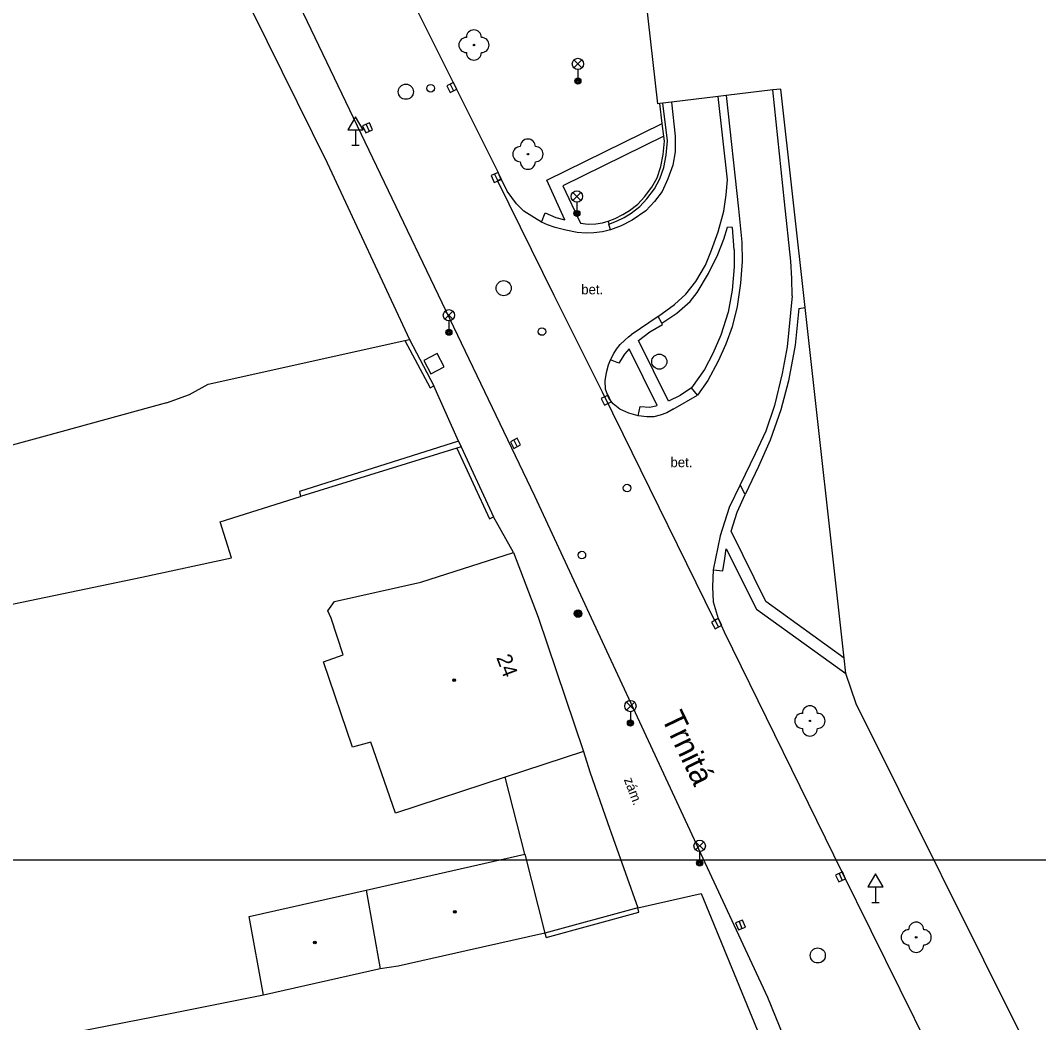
# Model space of a CAD drawing. Extents: x -598341 to -594502, y -1162301 to -1161406.
# Drawn here: x -597845.9 to -597778.6, y -1161741.3 to -1161675 of the extents above; entities that cross this region are included whole.
import ezdxf

# ---------------------------------------------------------------- set-up
doc = ezdxf.new("R2010")
doc.units = 0
for name, color, linetype in [('OKRAJ', 7, 'Continuous'), ('Vrstva 10', 7, 'Continuous'), ('Vrstva 11', 7, 'Continuous'), ('Vrstva 22', 7, 'Continuous'), ('Vrstva 25', 7, 'Continuous'), ('Vrstva 26', 7, 'Continuous'), ('Vrstva 27', 7, 'Continuous'), ('Vrstva 28', 7, 'Continuous'), ('Vrstva 31', 7, 'Continuous'), ('Vrstva 33', 7, 'Continuous'), ('Vrstva 34', 7, 'Continuous'), ('Vrstva 39', 7, 'Continuous'), ('Vrstva 40', 7, 'Continuous'), ('Vrstva 46', 7, 'Continuous'), ('Vrstva 49', 7, 'Continuous'), ('Vrstva 5', 7, 'Continuous'), ('Vrstva 7', 7, 'Continuous'), ('Vrstva 8', 7, 'Continuous')]:
    doc.layers.add(name, color=color, linetype=linetype)

msp = doc.modelspace()

# ---------------------------------------------------------------- linework, layer by layer
at = {"layer": 'OKRAJ'}
msp.add_line((-598126.97, -1161730.491), (-597723.77, -1161730.491), dxfattribs=at)
at = {"layer": 'Vrstva 10'}
for p, q in [((-597811.93, -1161706.44), (-597830.41, -1161667.86)), ((-597800.5, -1161731.02), (-597811.93, -1161706.44)), ((-597796.51, -1161739.61), (-597800.5, -1161731.02)), ((-597784.98, -1161767.75), (-597796.51, -1161739.61))]:
    msp.add_line(p, q, dxfattribs=at)
for points in [[(-597830.5, -1161652.45), (-597830.04, -1161653.37), (-597820.72, -1161672.28), (-597814.35, -1161685.04)], [(-597794.91, -1161693.2), (-597794.93, -1161692.06), (-597794.99, -1161690.9), (-597795.4, -1161686.98), (-597796.19, -1161679.58)], [(-597799.19, -1161685.52), (-597799.8, -1161680.01)], [(-597799.27, -1161679.95), (-597798.46, -1161687.44), (-597798.24, -1161689.64)], [(-597802.89, -1161680.38), (-597802.64, -1161682.63)], [(-597802.64, -1161682.63), (-597802.64, -1161683.68), (-597802.8, -1161684.55), (-597803.13, -1161685.47), (-597803.51, -1161686.29), (-597804, -1161686.95), (-597804.59, -1161687.58), (-597805.48, -1161688.19), (-597806.21, -1161688.57), (-597806.91, -1161688.83)], [(-597814.14, -1161685.47), (-597814.35, -1161685.04)], [(-597811.47, -1161688.32), (-597811.95, -1161688.05), (-597812.65, -1161687.59), (-597813.14, -1161687.11), (-597813.75, -1161686.28), (-597814.14, -1161685.47)], [(-597803.75, -1161694.55), (-597802.69, -1161693.77), (-597801.93, -1161693.09), (-597801.28, -1161692.25), (-597800.64, -1161691.17), (-597800.24, -1161690.18), (-597799.8, -1161688.96), (-597799.42, -1161687.59), (-597799.26, -1161686.51), (-597799.19, -1161685.52)], [(-597806.91, -1161688.83), (-597807.45, -1161688.97), (-597808.01, -1161689.04), (-597808.53, -1161689.06), (-597809.12, -1161689.02), (-597809.86, -1161688.86), (-597810.57, -1161688.68), (-597811.08, -1161688.5), (-597811.47, -1161688.32)], [(-597798.24, -1161689.64), (-597798.22, -1161690.93), (-597798.31, -1161692.36), (-597798.55, -1161693.91), (-597798.86, -1161695.25), (-597799.28, -1161696.4), (-597799.8, -1161697.51), (-597800.48, -1161698.8), (-597801.16, -1161699.77)], [(-597794.91, -1161693.2), (-597795.24, -1161696.57), (-597795.57, -1161698.34), (-597796.06, -1161700.45), (-597796.65, -1161702.14), (-597797.35, -1161703.65), (-597798.35, -1161705.7)], [(-597803.77, -1161694.56), (-597805.54, -1161695.77)], [(-597803.75, -1161694.55), (-597803.77, -1161694.56)], [(-597806.92, -1161697.42), (-597806.7, -1161697.02), (-597806.52, -1161696.73), (-597806.27, -1161696.42), (-597805.97, -1161696.12), (-597805.72, -1161695.91), (-597805.54, -1161695.77)], [(-597805.09, -1161701.14), (-597805.7, -1161700.96), (-597806.31, -1161700.69), (-597806.75, -1161700.34), (-597807.03, -1161699.96), (-597807.24, -1161699.37), (-597807.27, -1161698.83), (-597807.18, -1161698.26), (-597807.05, -1161697.76), (-597806.92, -1161697.42)], [(-597802.77, -1161700.7), (-597801.16, -1161699.77)], [(-597802.77, -1161700.7), (-597803.19, -1161700.93), (-597803.64, -1161701.1), (-597804.06, -1161701.19), (-597804.52, -1161701.21), (-597805.09, -1161701.14)], [(-597798.35, -1161705.7), (-597799.06, -1161707.2), (-597799.67, -1161709.06), (-597800.12, -1161711.31)], [(-597800.12, -1161711.31), (-597800.17, -1161712.44), (-597800.12, -1161713.43), (-597799.8, -1161714.53)], [(-597799.8, -1161714.53), (-597799.4, -1161715.41)], [(-597799.4, -1161715.41), (-597791.61, -1161731.3), (-597783.95, -1161746.81), (-597776.03, -1161762.85), (-597771.77, -1161771.52), (-597769.76, -1161775.59), (-597768.73, -1161777.72)]]:
    msp.add_lwpolyline(points, dxfattribs=at)
at = {"layer": 'Vrstva 11'}
for p, q in [((-597814.14, -1161685.47), (-597814.38, -1161685.59)), ((-597829.87, -1161739.44), (-597836.15, -1161740.7)), ((-597836.15, -1161740.7), (-597845.05, -1161742.44))]:
    msp.add_line(p, q, dxfattribs=at)
for points in [[(-597811.47, -1161688.32), (-597811.23, -1161687.7), (-597810.53, -1161688.01), (-597809.93, -1161688.18), (-597811.13, -1161685.55), (-597803.5, -1161681.79)], [(-597803.39, -1161682.64), (-597810.07, -1161685.93), (-597808.9, -1161688.4)], [(-597814.38, -1161685.59), (-597810.67, -1161693.15), (-597807.47, -1161699.55)], [(-597808.9, -1161688.4), (-597808.39, -1161688.45), (-597807.89, -1161688.43), (-597807.45, -1161688.38), (-597807.08, -1161688.27)], [(-597806.91, -1161688.83), (-597807.02, -1161688.46)], [(-597803.52, -1161695.01), (-597802.52, -1161694.34), (-597801.65, -1161693.57), (-597801.18, -1161692.98), (-597800.43, -1161691.73), (-597799.82, -1161690.47), (-597799.42, -1161689.46), (-597799.19, -1161688.66)], [(-597798.73, -1161690.15), (-597798.84, -1161688.68), (-597799.19, -1161688.66)], [(-597798.73, -1161690.15), (-597798.74, -1161691.29), (-597798.86, -1161692.82), (-597799.14, -1161694.27), (-597799.61, -1161695.8), (-597800.15, -1161697.02), (-597800.69, -1161698.08), (-597801.55, -1161699.29)], [(-597794.47, -1161694.04), (-597794.7, -1161696.46), (-597795.14, -1161698.81), (-597795.66, -1161700.73), (-597796.36, -1161702.75), (-597797.14, -1161704.49), (-597798.02, -1161706.33)], [(-597794.47, -1161694.04), (-597794.05, -1161693.97)], [(-597801.55, -1161699.29), (-597802.31, -1161699.79), (-597803.09, -1161700.16), (-597805.06, -1161696.15), (-597804.31, -1161695.58), (-597803.47, -1161695.1), (-597803.52, -1161695.01)], [(-597803.52, -1161695.01), (-597803.77, -1161694.56)], [(-597805.09, -1161701.14), (-597804.96, -1161700.52), (-597804.31, -1161700.56), (-597803.84, -1161700.46), (-597805.69, -1161696.7), (-597806, -1161697.06), (-597806.36, -1161697.65), (-597806.92, -1161697.42)], [(-597807.47, -1161699.55), (-597806.11, -1161702.33), (-597804.33, -1161705.91), (-597800.05, -1161714.62), (-597799.8, -1161714.53)], [(-597801.16, -1161699.77), (-597801.55, -1161699.29)], [(-597798.02, -1161706.33), (-597798.35, -1161705.7)], [(-597791.46, -1161717.16), (-597796.64, -1161713.41), (-597798.94, -1161708.76), (-597798.54, -1161707.5), (-597798.02, -1161706.33)], [(-597800.12, -1161711.31), (-597799.48, -1161711.38), (-597799.35, -1161710.56), (-597799.26, -1161709.93), (-597797.26, -1161713.92), (-597791.35, -1161718.18)], [(-597808.71, -1161723.34), (-597808.28, -1161724.67), (-597807.11, -1161728.04), (-597806.75, -1161729.08), (-597805.12, -1161733.68)]]:
    msp.add_lwpolyline(points, dxfattribs=at)
at = {"layer": 'Vrstva 22'}
for centre in [(-597815.95, -1161676.61), (-597812.38, -1161683.83), (-597793.73, -1161721.31), (-597786.7, -1161735.62)]:
    msp.add_circle(centre, 0.05, dxfattribs=at)
for centre, start, end in [((-597815.95, -1161676.11), 0, 180), ((-597816.45, -1161676.61), 90, 270), ((-597815.45, -1161676.61), 270, 90), ((-597815.95, -1161677.11), 180, 0), ((-597812.38, -1161683.33), 0, 180), ((-597812.88, -1161683.83), 90, 270), ((-597811.88, -1161683.83), 270, 90), ((-597812.38, -1161684.33), 180, 0), ((-597793.73, -1161720.81), 0, 180), ((-597794.23, -1161721.31), 90, 270), ((-597793.23, -1161721.31), 270, 90), ((-597793.73, -1161721.81), 180, 0), ((-597786.7, -1161735.12), 0, 180), ((-597787.2, -1161735.62), 90, 270), ((-597786.2, -1161735.62), 270, 90), ((-597786.7, -1161736.12), 180, 0)]:
    msp.add_arc(centre, 0.5, start, end, dxfattribs=at)
at = {"layer": 'Vrstva 25'}
for radius in [0.25, 0.2, 0.15, 0.1, 0.05]:
    msp.add_circle((-597809.06, -1161714.21), radius, dxfattribs=at)
at = {"layer": 'Vrstva 26'}
msp.add_lwpolyline([(-597819.265, -1161697.481), (-597818.799, -1161698.365), (-597817.915, -1161697.899), (-597818.381, -1161697.015)], close=True, dxfattribs=at)
at = {"layer": 'Vrstva 27'}
for p, q in [((-597817.521, -1161679.196), (-597817.299, -1161679.644)), ((-597823.082, -1161681.862), (-597822.878, -1161682.318)), ((-597814.582, -1161685.142), (-597814.378, -1161685.598)), ((-597807.308, -1161699.874), (-597807.092, -1161700.326)), ((-597813.318, -1161702.739), (-597813.082, -1161703.181)), ((-597800.006, -1161714.658), (-597799.774, -1161715.102)), ((-597791.803, -1161731.402), (-597791.597, -1161731.858)), ((-597798.415, -1161734.579), (-597798.225, -1161735.041))]:
    msp.add_line(p, q, dxfattribs=at)
for points in [[(-597817.745, -1161679.307), (-597817.523, -1161679.755), (-597817.075, -1161679.533), (-597817.297, -1161679.085)], [(-597823.31, -1161681.965), (-597823.106, -1161682.421), (-597822.65, -1161682.216), (-597822.854, -1161681.76)], [(-597814.81, -1161685.245), (-597814.606, -1161685.701), (-597814.15, -1161685.496), (-597814.354, -1161685.04)], [(-597807.533, -1161699.982), (-597807.318, -1161700.433), (-597806.867, -1161700.218), (-597807.082, -1161699.767)], [(-597813.538, -1161702.857), (-597813.303, -1161703.298), (-597812.862, -1161703.063), (-597813.097, -1161702.622)], [(-597800.227, -1161714.774), (-597799.996, -1161715.217), (-597799.553, -1161714.986), (-597799.784, -1161714.543)], [(-597792.031, -1161731.506), (-597791.824, -1161731.961), (-597791.369, -1161731.754), (-597791.576, -1161731.299)], [(-597798.646, -1161734.674), (-597798.456, -1161735.136), (-597797.994, -1161734.946), (-597798.184, -1161734.484)]]:
    msp.add_lwpolyline(points, close=True, dxfattribs=at)
for centre in [(-597820.45, -1161679.7), (-597813.98, -1161692.69), (-597803.69, -1161697.55), (-597793.21, -1161736.82)]:
    msp.add_circle(centre, 0.5, dxfattribs=at)
at = {"layer": 'Vrstva 28'}
for centre in [(-597818.81, -1161679.47), (-597811.45, -1161695.56), (-597805.82, -1161705.91)]:
    msp.add_circle(centre, 0.25, dxfattribs=at)
at = {"layer": 'Vrstva 31'}
msp.add_circle((-597808.81, -1161710.34), 0.25, dxfattribs=at)
at = {"layer": 'Vrstva 33'}
for p, q in [((-597809.335, -1161678.13), (-597808.805, -1161677.6)), ((-597809.335, -1161677.6), (-597808.805, -1161678.13)), ((-597809.07, -1161678.24), (-597809.07, -1161678.99)), ((-597809.405, -1161686.89), (-597808.875, -1161686.36)), ((-597809.405, -1161686.36), (-597808.875, -1161686.89)), ((-597809.14, -1161687), (-597809.14, -1161687.75)), ((-597817.865, -1161694.75), (-597817.335, -1161694.22)), ((-597817.865, -1161694.22), (-597817.335, -1161694.75)), ((-597817.6, -1161694.86), (-597817.6, -1161695.61)), ((-597805.865, -1161720.59), (-597805.335, -1161720.06)), ((-597805.865, -1161720.06), (-597805.335, -1161720.59)), ((-597805.6, -1161720.7), (-597805.6, -1161721.45)), ((-597801.285, -1161729.84), (-597800.755, -1161729.31)), ((-597801.285, -1161729.31), (-597800.755, -1161729.84)), ((-597801.02, -1161729.95), (-597801.02, -1161730.7))]:
    msp.add_line(p, q, dxfattribs=at)
for centre, radius in [((-597809.07, -1161677.865), 0.375), ((-597809.07, -1161678.99), 0.2), ((-597809.07, -1161678.99), 0.145), ((-597809.07, -1161678.99), 0.0876), ((-597809.14, -1161686.625), 0.375), ((-597809.14, -1161687.75), 0.2), ((-597809.14, -1161687.75), 0.145), ((-597809.14, -1161687.75), 0.0876), ((-597817.6, -1161694.485), 0.375), ((-597817.6, -1161695.61), 0.2), ((-597817.6, -1161695.61), 0.145), ((-597817.6, -1161695.61), 0.0876), ((-597805.6, -1161720.325), 0.375), ((-597805.6, -1161721.45), 0.2), ((-597805.6, -1161721.45), 0.145), ((-597805.6, -1161721.45), 0.0876), ((-597801.02, -1161729.575), 0.375), ((-597801.02, -1161730.7), 0.2), ((-597801.02, -1161730.7), 0.145), ((-597801.02, -1161730.7), 0.0876)]:
    msp.add_circle(centre, radius, dxfattribs=at)
at = {"layer": 'Vrstva 34'}
for p, q in [((-597823.78, -1161682.222), (-597823.78, -1161683.24)), ((-597824.03, -1161683.24), (-597823.53, -1161683.24)), ((-597789.39, -1161732.292), (-597789.39, -1161733.31)), ((-597789.64, -1161733.31), (-597789.14, -1161733.31))]:
    msp.add_line(p, q, dxfattribs=at)
for points in [[(-597824.28, -1161682.222), (-597823.28, -1161682.222), (-597823.78, -1161681.356)], [(-597789.89, -1161732.292), (-597788.89, -1161732.292), (-597789.39, -1161731.426)]]:
    msp.add_lwpolyline(points, close=True, dxfattribs=at)
at = {"layer": 'Vrstva 39'}
for centre, radius in [((-597817.26, -1161718.61), 0.09), ((-597817.26, -1161718.61), 0.0398), ((-597817.22, -1161733.93), 0.09), ((-597817.22, -1161733.93), 0.0398), ((-597826.47, -1161735.97), 0.09), ((-597826.47, -1161735.97), 0.0398)]:
    msp.add_circle(centre, radius, dxfattribs=at)
at = {"layer": 'Vrstva 5'}
for p, q in [((-597803.79, -1161680.49), (-597807.22, -1161650.28)), ((-597796.19, -1161679.58), (-597799.27, -1161679.95)), ((-597795.66, -1161679.52), (-597796.19, -1161679.58)), ((-597794.05, -1161693.97), (-597795.66, -1161679.52)), ((-597799.8, -1161680.01), (-597802.89, -1161680.38)), ((-597799.27, -1161679.95), (-597799.8, -1161680.01)), ((-597803.66, -1161680.48), (-597803.79, -1161680.49)), ((-597803.46, -1161680.45), (-597803.66, -1161680.48)), ((-597802.89, -1161680.38), (-597803.46, -1161680.45)), ((-597791.46, -1161717.16), (-597794.05, -1161693.97)), ((-597819.46, -1161712.13), (-597813.34, -1161710.17)), ((-597813.34, -1161710.17), (-597811.71, -1161714.44)), ((-597825.17, -1161713.42), (-597819.46, -1161712.13)), ((-597825.6, -1161714.04), (-597825.17, -1161713.42)), ((-597825.39, -1161714.51), (-597825.6, -1161714.04)), ((-597824.6, -1161716.94), (-597825.39, -1161714.51)), ((-597811.71, -1161714.44), (-597808.71, -1161723.34)), ((-597825.9, -1161717.4), (-597824.6, -1161716.94)), ((-597791.35, -1161718.18), (-597791.46, -1161717.16)), ((-597823.97, -1161723.04), (-597825.9, -1161717.4)), ((-597790.68, -1161720.18), (-597791.35, -1161718.18)), ((-597767.04, -1161767.55), (-597790.68, -1161720.18)), ((-597822.76, -1161722.71), (-597823.97, -1161723.04)), ((-597821.14, -1161727.42), (-597822.76, -1161722.71)), ((-597808.71, -1161723.34), (-597813.89, -1161725.04)), ((-597813.89, -1161725.04), (-597821.14, -1161727.42)), ((-597823.08, -1161732.5), (-597812.59, -1161730.12)), ((-597812.59, -1161730.12), (-597811.26, -1161735.34)), ((-597830.81, -1161734.25), (-597823.08, -1161732.5)), ((-597823.08, -1161732.5), (-597822.14, -1161737.7)), ((-597829.87, -1161739.44), (-597830.81, -1161734.25)), ((-597811.26, -1161735.34), (-597816.46, -1161736.51)), ((-597816.46, -1161736.51), (-597820.97, -1161737.54)), ((-597820.97, -1161737.54), (-597822.14, -1161737.7)), ((-597822.14, -1161737.7), (-597829.87, -1161739.44))]:
    msp.add_line(p, q, dxfattribs=at)
at = {"layer": 'Vrstva 7'}
for p, q in [((-597833.1, -1161669.29), (-597829.64, -1161676.34)), ((-597829.64, -1161676.34), (-597825.66, -1161684.4)), ((-597825.66, -1161684.4), (-597820.21, -1161696.09)), ((-597807.08, -1161688.27), (-597807.02, -1161688.46)), ((-597820.21, -1161696.09), (-597818.59, -1161699.15)), ((-597836.27, -1161700.27), (-597844.31, -1161702.47)), ((-597844.31, -1161702.47), (-597855.19, -1161705.47)), ((-597816.79, -1161703.18), (-597817.08, -1161703.27)), ((-597817.08, -1161703.27), (-597827.42, -1161706.48)), ((-597832.74, -1161708.14), (-597827.42, -1161706.48)), ((-597831.98, -1161710.53), (-597832.74, -1161708.14)), ((-597837.91, -1161711.81), (-597831.98, -1161710.53)), ((-597853.03, -1161714.95), (-597837.91, -1161711.81))]:
    msp.add_line(p, q, dxfattribs=at)
for points in [[(-597803.5, -1161681.79), (-597803.66, -1161680.48)], [(-597803.15, -1161682.94), (-597803.46, -1161680.45)], [(-597803.39, -1161682.64), (-597803.5, -1161681.79)], [(-597807.08, -1161688.27), (-597806.6, -1161688.08), (-597806.1, -1161687.83), (-597805.66, -1161687.55), (-597805.12, -1161687.13), (-597804.66, -1161686.65), (-597804.18, -1161686.02), (-597803.84, -1161685.39), (-597803.58, -1161684.65), (-597803.43, -1161683.86), (-597803.35, -1161682.97)], [(-597807.02, -1161688.46), (-597806.51, -1161688.26), (-597806.01, -1161688.01), (-597805.54, -1161687.72), (-597804.98, -1161687.28), (-597804.51, -1161686.78), (-597804.01, -1161686.13), (-597803.65, -1161685.47), (-597803.38, -1161684.7), (-597803.23, -1161683.89), (-597803.15, -1161682.94)], [(-597803.35, -1161682.97), (-597803.39, -1161682.64)], [(-597836.27, -1161700.27), (-597834.76, -1161699.73), (-597833.53, -1161699.04), (-597820.51, -1161696.16)], [(-597820.51, -1161696.16), (-597820.21, -1161696.09)], [(-597820.51, -1161696.16), (-597818.85, -1161699.29), (-597818.59, -1161699.15)], [(-597816.96, -1161702.81), (-597827.48, -1161706.13), (-597827.42, -1161706.48)], [(-597816.96, -1161702.81), (-597816.79, -1161703.18)], [(-597816.79, -1161703.18), (-597814.66, -1161707.82)], [(-597817.08, -1161703.27), (-597814.93, -1161707.94), (-597814.66, -1161707.82)], [(-597805.12, -1161733.68), (-597800.91, -1161732.73), (-597793.87, -1161749.9)], [(-597811.26, -1161735.34), (-597811.18, -1161735.63), (-597805.04, -1161733.97), (-597805.12, -1161733.68)], [(-597805.12, -1161733.68), (-597811.26, -1161735.34)]]:
    msp.add_lwpolyline(points, dxfattribs=at)
at = {"layer": 'Vrstva 8'}
for p, q in [((-597816.96, -1161702.81), (-597818.59, -1161699.15)), ((-597813.34, -1161710.17), (-597814.66, -1161707.82)), ((-597812.59, -1161730.12), (-597813.89, -1161725.04))]:
    msp.add_line(p, q, dxfattribs=at)

# ---------------------------------------------------------------- texts
at = {"layer": 'Vrstva 40'}
for p in [(-597808.85, -1161693.1), (-597802.95, -1161704.53)]:
    msp.add_text('bet.', height=0.65, dxfattribs=at).set_placement(p)
msp.add_text('zám.', height=0.65, rotation=290.68638, dxfattribs=at).set_placement((-597806.04, -1161725.19))
at = {"layer": 'Vrstva 46'}
msp.add_text('24', height=1, rotation=290.61, dxfattribs=at).set_placement((-597814.48, -1161717.12))
at = {"layer": 'Vrstva 49'}
msp.add_text('Trnitá', height=1.5, rotation=295.68, dxfattribs=at).set_placement((-597803.58, -1161721.1))

doc.saveas('drawing.dxf')
